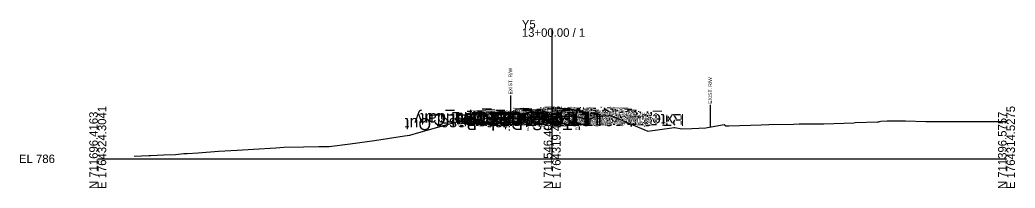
# Model space of a CAD drawing. Extents: x -26 to 303, y -10 to 4039.
# Drawn here: x -25.7 to 302.8, y 2990.3 to 3046 of the extents above; entities that cross this region are included whole.
import ezdxf

# ---------------------------------------------------------------- set-up
doc = ezdxf.new("R2010")
doc.units = 0
for name, color, linetype in [('Default', 7, 'Continuous'), ('Exist Cross Section Cell', 7, 'Continuous'), ('Exist XS Center Line Elevation Label', 7, 'Continuous'), ('Exist XS Ground Line', 7, 'Continuous'), ('Old_Level_10', 7, 'Continuous'), ('Prop CMT Pvmt Course 1', 7, 'Continuous'), ('Prop CMT Pvmt Surface', 7, 'Continuous'), ('Prop XS Earthwork Shape', 7, 'Continuous'), ('Prop XS SE Text', 7, 'Continuous'), ('Scratch_Level_4', 7, 'Continuous')]:
    doc.layers.add(name, color=color, linetype=linetype)

msp = doc.modelspace()

# ---------------------------------------------------------------- linework, layer by layer
at = {"layer": 'Exist Cross Section Cell'}
for p, q in [((150, 3000), (150, 3043.15)), ((0, 3000), (150, 3000)), ((150, 3000), (300, 3000))]:
    msp.add_line(p, q, dxfattribs=at)
at = {"layer": 'Exist XS Ground Line'}
msp.add_lwpolyline([(11.99, 3000.84), (16.87, 3001.05), (17.56, 3001.11), (21.68, 3001.33), (25.72, 3001.48), (28.42, 3001.71), (29.52, 3001.75), (33.15, 3001.95), (39.9, 3002.56), (45.99, 3002.89), (51.4, 3003.19), (58.77, 3003.62), (61.41, 3003.83), (67.94, 3003.95), (72.94, 3004.06), (76.45, 3004.11), (83.3, 3004.97), (91.42, 3006.09), (101.29, 3007.55), (103.06, 3007.82), (106.05, 3008.65), (121.28, 3012.97), (126.28, 3013.22), (131.45, 3013.53), (138.62, 3013.62), (141.96, 3013.74), (142.39, 3013.79), (142.74, 3013.83), (144.39, 3013.9), (145.24, 3013.93), (146.04, 3013.97), (147.74, 3014.04), (149.57, 3014.08), (150.25, 3014.1), (152.15, 3014.08), (152.75, 3014.08), (153.31, 3014.07), (155.49, 3014.07), (156.24, 3014.07), (156.61, 3014.08), (157.73, 3014.08), (158.08, 3014.04), (160.37, 3013.35), (161.74, 3012.89), (163.32, 3013.6), (163.92, 3013.88), (166.36, 3014.21), (169.37, 3014.38), (171.95, 3013.22), (181.61, 3009.13), (189.52, 3010.3), (190.23, 3010.38), (190.55, 3010.31), (192.82, 3009.95), (196.08, 3010), (200.79, 3010.22), (204.9, 3011.06), (206.8, 3011.38), (207.3, 3010.88), (208.3, 3010.93), (218.97, 3011.24), (221.51, 3011.32), (229.72, 3011.44), (231.52, 3011.53), (239.69, 3011.61), (249.63, 3011.85), (250, 3011.96), (257.37, 3012.2), (257.89, 3012.21), (258.05, 3012.35), (258.53, 3012.49), (260.58, 3012.51), (263.05, 3012.53), (264.32, 3012.57), (266.08, 3012.56), (266.63, 3012.56), (273.33, 3012.38), (300, 3012.38)], dxfattribs=at)
at = {"layer": 'Old_Level_10'}
for p, q in [((136.23, 3020.99), (136.23, 3013.59)), ((202.15, 3017.9), (202.15, 3010.49)), ((141.96, 3013.74), (141.96, 3011.69)), ((158.08, 3014.04), (158.08, 3011.99))]:
    msp.add_line(p, q, dxfattribs=at)
at = {"layer": 'Prop CMT Pvmt Course 1'}
for points in [[(141.96, 3013.68), (150, 3013.96)], [(150, 3013.84), (150, 3014.09)], [(150, 3014.09), (158.08, 3014.05)], [(150, 3013.96), (150, 3013.84), (150, 3013.84)], [(158.08, 3013.92), (150, 3013.96)]]:
    msp.add_lwpolyline(points, dxfattribs=at)
at = {"layer": 'Prop CMT Pvmt Surface'}
msp.add_line((141.96, 3013.81), (141.96, 3013.74), dxfattribs=at)
for points in [[(150, 3014.09), (141.96, 3013.81)], [(150, 3014.09), (158.08, 3014.05)]]:
    msp.add_lwpolyline(points, dxfattribs=at)
at = {"layer": 'Prop XS Earthwork Shape'}
for points in [[(141.96, 3013.81), (141.96, 3013.74), (142.39, 3013.79), (142.74, 3013.83), (143.94, 3013.88)], [(157.73, 3014.08), (158.08, 3014.05), (150, 3014.09), (143.94, 3013.88), (144.39, 3013.9), (145.24, 3013.93), (146.04, 3013.97), (147.74, 3014.04), (149.57, 3014.08), (150.25, 3014.1), (152.15, 3014.08), (152.75, 3014.08), (153.31, 3014.07), (155.49, 3014.07), (156.24, 3014.07), (156.61, 3014.08)]]:
    msp.add_lwpolyline(points, close=True, dxfattribs=at)

# ---------------------------------------------------------------- texts
at = {"layer": 'Default'}
msp.add_text('-', height=0.0001, dxfattribs=at).set_placement((0, 3000))
at = {"layer": 'Exist Cross Section Cell'}
for s, p in [('Y5', (140, 3043.15)), ('13+00.00 / 1', (140, 3040.35)), ('EL 786', (-26, 2998.6))]:
    msp.add_text(s, height=2.8, dxfattribs=at).set_placement(p)
for s, p in [('E 1764324.3041', (2.8, 2990)), ('E 1764319.4158', (152.8, 2990)), ('E 1764314.5275', (302.8, 2990)), ('N 711696.4163', (0, 2990)), ('N 711546.4960', (150, 2990)), ('N 711396.5757', (300, 2990))]:
    msp.add_text(s, height=2.8, rotation=90, dxfattribs=at).set_placement(p)
at = {"layer": 'Exist XS Center Line Elevation Label'}
msp.add_text('800.09', height=1, dxfattribs=at).set_placement((147.87, 3012.09))
at = {"layer": 'Old_Level_10'}
for s, height, p in [('EXIST. R/W', 1.181, (136.82, 3021.3)), ('EXIST. R/W', 1.181, (202.74, 3018.2)), ('EOP', 0.787, (142.35, 3009.29)), ('EOP', 0.787, (158.48, 3009.59))]:
    msp.add_text(s, height=height, rotation=90, dxfattribs=at).set_placement(p)
at = {"layer": 'Prop XS SE Text'}
for rotation, p in [(2.0045, (143.28, 3014.86)), (359.7135, (151.39, 3015.08))]:
    msp.add_text('EXIST.', height=1.5, rotation=rotation, dxfattribs=at).set_placement(p)
at = {"layer": 'Scratch_Level_4'}
for s, p in [('Exterior Boundary', (147.35, 3015.08)), ('LT_Slope_Cut', (140.64, 3015.08)), ('LT_Sub_Trench_Out', (166.46, 3014.87)), ('LT_GS_OS_CTL', (157.57, 3015.49)), ('LT_PS3_Shelf_Out', (165.54, 3015.21)), ('LT_PV1_OEEOP', (161.65, 3015.68)), ('LT_PV2_OEEOP', (162.66, 3015.56)), ('LT_PV3_OEEOP', (162.69, 3015.23)), ('LT_Sub_OEEOP', (162.13, 3014.89)), ('LT_PV1_OEOT', (159.59, 3015.81)), ('LT_PS1_OEOP', (159.86, 3015.81)), ('LT_PS3_OEOP', (160.3, 3015.21)), ('LT_PS2_OEOP', (160.61, 3015.55)), ('LT_PV2_OEOT', (160.6, 3015.56)), ('LT_PV3_OEOT', (160.63, 3015.23)), ('LT_Sub_OEOT', (160.06, 3014.89)), ('RT_PV1_IEEOP', (169.32, 3015.96)), ('LT_PV1_IEEOP', (168.82, 3015.96)), ('RT_PV2_IEEOP', (170.33, 3015.84)), ('LT_PV2_IEEOP', (169.82, 3015.84)), ('RT_Sub_Trench_Out', (184.97, 3015.11)), ('RT_PV1_OEEOP', (178.29, 3015.92)), ('RT_PS3_Shelf_Out', (183.37, 3015.45)), ('PV1_PGL', (160.68, 3016.09)), ('RT_PV2_OEEOP', (179.29, 3015.8)), ('RT_PV3_OEEOP', (179.32, 3015.47)), ('RT_Sub_OEEOP', (178.76, 3015.13)), ('RT_PV1_OEOT', (176.22, 3016.05)), ('PV2_PGL', (161.68, 3015.84)), ('RT_PS1_OEOP', (176.49, 3016.05)), ('RT_PV2_OEOT', (177.23, 3015.8)), ('RT_PV3_OEOT', (177.26, 3015.47)), ('RT_Sub_OEOT', (176.7, 3015.13)), ('RT_PS2_OEOP', (177.75, 3015.79)), ('RT_PS3_OEOP', (178.12, 3015.45)), ('RT_GS_OS_CTL', (182.2, 3015.73)), ('RT_Sub_OSS_DLT', (193.35, 3014.82)), ('RT_Slope_Fill', (180.84, 3015.49)), ('Exterior Boundary', (193.67, 3014.82)), ('LT_SS_Ditch_Base_Out', (159.68, 3013.49)), ('LT_Sub_OSS_DLT', (157.97, 3014.75))]:
    msp.add_text(s, height=4, rotation=180, dxfattribs=at).set_placement(p)

doc.saveas('drawing.dxf')
